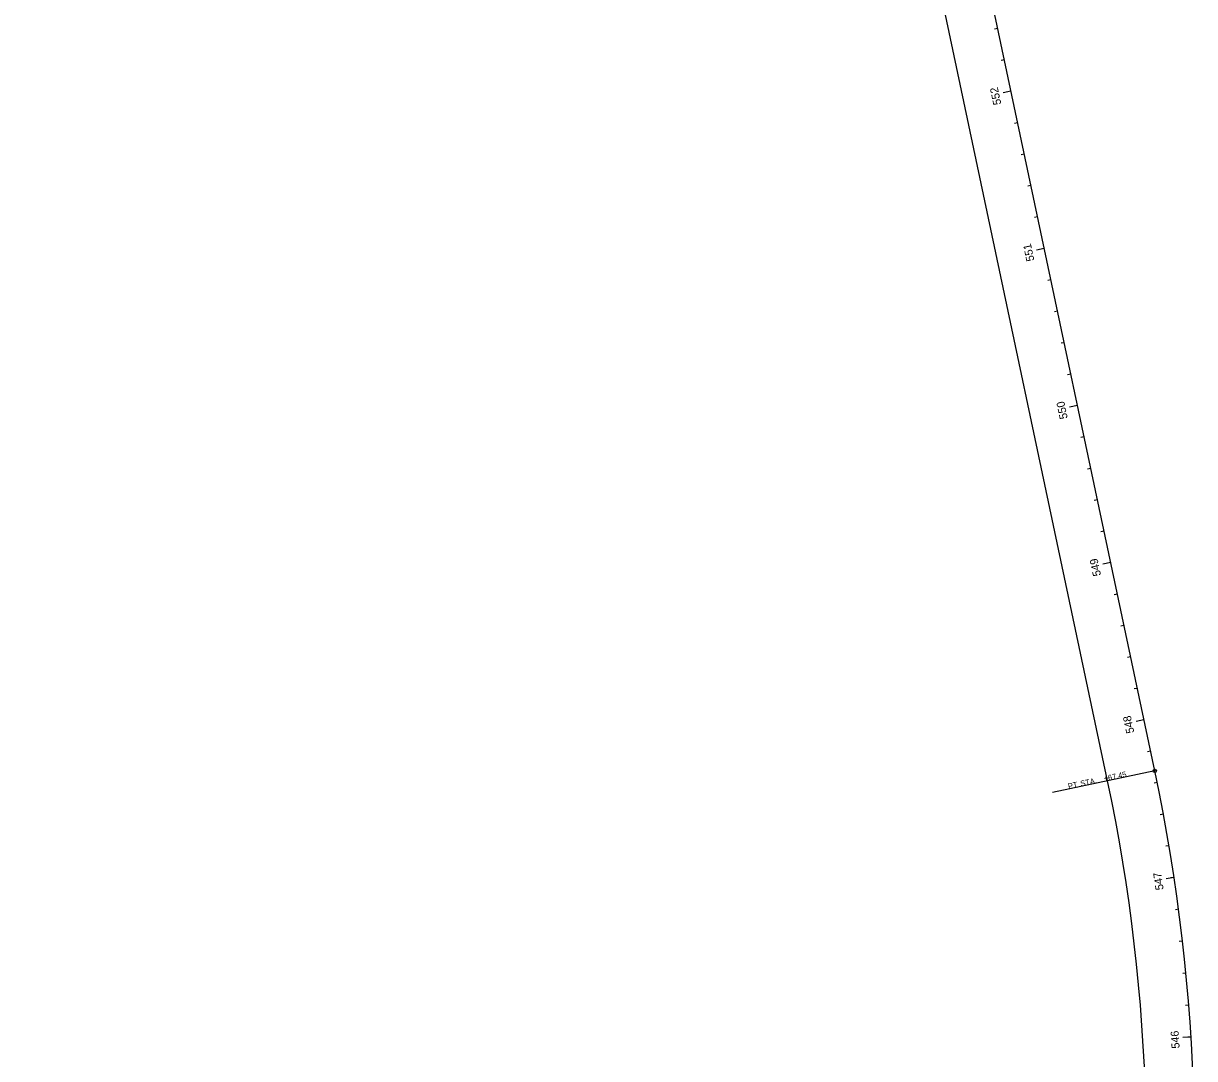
# Model space of a CAD drawing. Extents: x 2003883 to 2007688, y 399149 to 412300.
# Drawn here: x 2005520 to 2006249, y 401995 to 402640 of the extents above; entities that cross this region are included whole.
import ezdxf

# ---------------------------------------------------------------- set-up
doc = ezdxf.new("R2010")
doc.units = 0
for name, color, linetype in [('BaselineSurvey', 7, 'Continuous'), ('ConstLines', 7, 'Continuous'), ('Default', 7, 'Continuous'), ('TextAlgnCardinalPnt', 7, 'Continuous'), ('TextAlgnStation100', 7, 'Continuous'), ('TextAlgnStation1000', 7, 'Continuous'), ('TextAlgnStation500', 7, 'Continuous'), ('TextAlgnStation5000', 7, 'Continuous'), ('TextAlgnTicks100', 7, 'Continuous'), ('TextAlgnTicks1000', 7, 'Continuous'), ('TextAlgnTicks500', 7, 'Continuous'), ('TextAlgnTicks5000', 7, 'Continuous')]:
    doc.layers.add(name, color=color, linetype=linetype)

msp = doc.modelspace()

# ---------------------------------------------------------------- linework, layer by layer
at = {"layer": 'BaselineSurvey'}
msp.add_line((2006223.92, 402174.38), (2005094.48, 407516.05), dxfattribs=at)
msp.add_arc((2005102.8, 401937.33), 1145.91, 329.99111, 11.93882, dxfattribs=at)
at = {"layer": 'ConstLines'}
msp.add_line((2006194.57, 402168.18), (2005065.13, 407509.84), dxfattribs=at)
msp.add_arc((2005102.8, 401937.33), 1115.91, 329.99111, 11.93882, dxfattribs=at)
at = {"layer": 'Default'}
msp.add_line((2006223.92, 402174.38), (2005094.48, 407516.05), dxfattribs=at)
msp.add_arc((2005102.8, 401937.33), 1145.91, 329.99111, 11.93882, dxfattribs=at)
at = {"layer": 'TextAlgnCardinalPnt'}
msp.add_line((2006223.92, 402174.38), (2006160.33, 402160.94), dxfattribs=at)
msp.add_circle((2006223.92, 402174.38), 1, dxfattribs=at)
at = {"layer": 'TextAlgnTicks100'}
for p, q in [((2006126.17, 402636.71), (2006124.21, 402636.29)), ((2006130.31, 402617.14), (2006128.35, 402616.73)), ((2006134.44, 402597.57), (2006129.55, 402596.54)), ((2006138.58, 402578), (2006136.63, 402577.59)), ((2006142.72, 402558.44), (2006140.76, 402558.02)), ((2006146.86, 402538.87), (2006144.9, 402538.46)), ((2006150.99, 402519.3), (2006149.04, 402518.89)), ((2006155.13, 402499.74), (2006150.24, 402498.7)), ((2006159.27, 402480.17), (2006157.31, 402479.75)), ((2006163.41, 402460.6), (2006161.45, 402460.19)), ((2006167.54, 402441.03), (2006165.59, 402440.62)), ((2006171.68, 402421.47), (2006169.72, 402421.05)), ((2006175.82, 402401.9), (2006170.93, 402400.86)), ((2006179.96, 402382.33), (2006178, 402381.92)), ((2006184.09, 402362.76), (2006182.14, 402362.35)), ((2006188.23, 402343.2), (2006186.27, 402342.78)), ((2006192.37, 402323.63), (2006190.41, 402323.22)), ((2006196.51, 402304.06), (2006191.61, 402303.03)), ((2006200.64, 402284.49), (2006198.69, 402284.08)), ((2006204.78, 402264.93), (2006202.82, 402264.51)), ((2006208.92, 402245.36), (2006206.96, 402244.95)), ((2006213.05, 402225.79), (2006211.1, 402225.38)), ((2006217.19, 402206.22), (2006212.3, 402205.19)), ((2006221.33, 402186.66), (2006219.37, 402186.24)), ((2006225.44, 402167.08), (2006223.48, 402166.68)), ((2006229.28, 402147.46), (2006227.32, 402147.09)), ((2006232.78, 402127.77), (2006230.81, 402127.43)), ((2006235.93, 402108.02), (2006230.98, 402107.27)), ((2006238.73, 402088.21), (2006236.75, 402087.95)), ((2006241.2, 402068.37), (2006239.21, 402068.14)), ((2006243.31, 402048.48), (2006241.32, 402048.28)), ((2006245.07, 402028.56), (2006243.08, 402028.4)), ((2006246.49, 402008.61), (2006241.5, 402008.3))]:
    msp.add_line(p, q, dxfattribs=at)
at = {"layer": 'TextAlgnTicks1000'}
for p, q in [((2006134.44, 402597.57), (2006132.49, 402597.16)), ((2006175.82, 402401.9), (2006170.93, 402400.86)), ((2006217.19, 402206.22), (2006215.24, 402205.81)), ((2006246.49, 402008.61), (2006244.5, 402008.48))]:
    msp.add_line(p, q, dxfattribs=at)
at = {"layer": 'TextAlgnTicks500'}
for p, q in [((2006134.44, 402597.57), (2006132.49, 402597.16)), ((2006155.13, 402499.74), (2006153.18, 402499.32)), ((2006175.82, 402401.9), (2006170.93, 402400.86)), ((2006196.51, 402304.06), (2006194.55, 402303.65)), ((2006217.19, 402206.22), (2006215.24, 402205.81)), ((2006235.93, 402108.02), (2006233.95, 402107.72)), ((2006246.49, 402008.61), (2006244.5, 402008.48))]:
    msp.add_line(p, q, dxfattribs=at)
at = {"layer": 'TextAlgnTicks5000'}
msp.add_line((2006175.82, 402401.9), (2006170.93, 402400.86), dxfattribs=at)

# ---------------------------------------------------------------- texts
at = {"layer": 'TextAlgnCardinalPnt'}
for s, p in [('+67.45', (2006192.54, 402167.75)), ('PT', (2006170.33, 402163.05)), (' STA. ', (2006176.77, 402164.41))]:
    msp.add_text(s, height=3.48, rotation=11.93882, dxfattribs=at).set_placement(p)
at = {"layer": 'TextAlgnStation100'}
for s, rotation, p in [('552', 101.93882, (2006128.46, 402589.6)), ('551', 101.93882, (2006149.06, 402492.21)), ('550', 101.93882, (2006169.82, 402393.99)), ('549', 101.93882, (2006190.51, 402296.14)), ('548', 101.93882, (2006211.21, 402198.27)), ('547', 98.56616, (2006229.47, 402100.52)), ('546', 93.56614, (2006239.41, 402001.65))]:
    msp.add_text(s, height=4.98, rotation=rotation, dxfattribs=at).set_placement(p)
at = {"layer": 'TextAlgnStation1000'}
msp.add_text('550', height=4.98, rotation=101.93882, dxfattribs=at).set_placement((2006169.82, 402393.99))
at = {"layer": 'TextAlgnStation500'}
msp.add_text('550', height=4.98, rotation=101.93882, dxfattribs=at).set_placement((2006169.82, 402393.99))
at = {"layer": 'TextAlgnStation5000'}
msp.add_text('550', height=4.98, rotation=101.93882, dxfattribs=at).set_placement((2006169.82, 402393.99))

doc.saveas('drawing.dxf')
